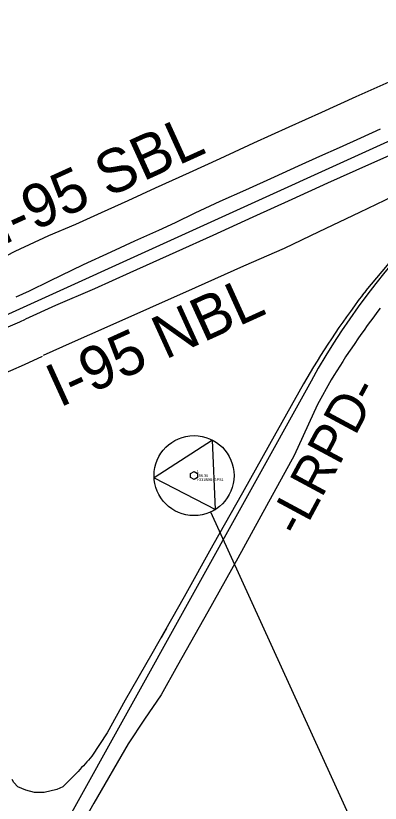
# Model space of a CAD drawing. Extents: x 2243531 to 2252747, y 658714 to 667210.
# Drawn here: x 2247806 to 2248142, y 662389 to 663115 of the extents above; entities that cross this region are included whole.
import ezdxf

# ---------------------------------------------------------------- set-up
doc = ezdxf.new("R2010")
doc.units = 0
for name, color, linetype in [('CTL GPS Vertical CELL', 7, 'Continuous'), ('CTL GPS Vertical Cogo Comment', 7, 'Continuous'), ('CTL GPS Vertical Cogo Elevation', 7, 'Continuous'), ('CTL GPS Vertical Cogo Number', 7, 'Continuous'), ('CTL NGS Horizontal CELL', 7, 'Continuous'), ('Exist Roads EOP', 7, 'Continuous'), ('Exist Roads EOP Text', 7, 'Continuous'), ('Prop Horizontal Alignment', 7, 'Continuous')]:
    doc.layers.add(name, color=color, linetype=linetype)

msp = doc.modelspace()

# ---------------------------------------------------------------- linework, layer by layer
at = {"layer": 'CTL GPS Vertical CELL'}
msp.add_line((2247970.45, 662691.36), (2247970.45, 662691.36), dxfattribs=at)
msp.add_lwpolyline([(2247967.22, 662693.23), (2247970.47, 662695.04), (2247973.72, 662693.26), (2247973.67, 662689.53), (2247970.42, 662687.64), (2247967.22, 662689.46)], close=True, dxfattribs=at)
at = {"layer": 'CTL NGS Horizontal CELL'}
for p, q in [((2247970.45, 662691.36), (2247970.45, 662691.36)), ((2247985.74, 662657.8), (2248187.57, 662214.89))]:
    msp.add_line(p, q, dxfattribs=at)
msp.add_lwpolyline([(2247933.59, 662689.43), (2247990.24, 662660.19), (2247987.36, 662724.13), (2247933.59, 662689.43)], dxfattribs=at)
msp.add_circle((2247970.45, 662691.36), 36.87, dxfattribs=at)
at = {"layer": 'Exist Roads EOP'}
msp.add_line((2248128.89, 662862.01), (2248125.5, 662857.61), dxfattribs=at)
for points in [[(2247790.71, 662890.62), (2247805.57, 662898.29), (2247836.78, 662912.86), (2247861.63, 662923.16), (2247885.32, 662933.83), (2247909.61, 662945.06), (2247935.04, 662956.66), (2247966.34, 662970.9), (2247994.49, 662983.87), (2248025.59, 662998.19), (2248058.08, 663012.97), (2248088.08, 663026.44), (2248119.82, 663041.08), (2248150.21, 663054.44), (2248181.1, 663069.6), (2248218.38, 663087.19), (2248245.39, 663099.49), (2248287.88, 663118.8), (2248325.22, 663134.87), (2248357.59, 663149.14), (2248375.51, 663157.12), (2248384.78, 663161.44)], [(2248461.34, 663127.8), (2248423.69, 663110.61), (2248387, 663094.02), (2248349.12, 663076.79), (2248316.15, 663062.19), (2248279.66, 663045.57), (2248238.72, 663026.91), (2248203.09, 663010.67), (2248166.49, 662993.47), (2248131.09, 662977.98), (2248093.34, 662960.9), (2248060.54, 662946.01), (2248024.51, 662929.58), (2247987.81, 662912.88), (2247953.6, 662897.46), (2247911.13, 662878.2), (2247878.83, 662863.52), (2247842.91, 662848.25), (2247815.2, 662835.56)], [(2248142.04, 663010.79), (2248123.7, 663002.54), (2248104.21, 662993.66), (2248086.01, 662985.57), (2248066.33, 662976.62), (2248044.2, 662966.53), (2248017.78, 662954.61), (2247994.22, 662943.99), (2247971.06, 662933.49), (2247952.96, 662924.57), (2247937.83, 662917.26), (2247915.51, 662907.4), (2247893.88, 662897.53), (2247868.29, 662885.73), (2247837.31, 662870.57), (2247818.47, 662861.37), (2247806.29, 662855.84)], [(2247831.65, 662802.33), (2247858.38, 662814.46), (2247890.52, 662828.54), (2247929.75, 662846.07), (2247971.89, 662864.9), (2248016.34, 662884.69), (2248053.87, 662901.09), (2248085.69, 662916.48), (2248123.17, 662934.34), (2248153.89, 662949.09), (2248186.42, 662964.72), (2248216.92, 662976.74), (2248221.9, 662965.48), (2248194.06, 662935.8), (2248165.12, 662904.72)], [(2248128.89, 662862.01), (2248165.12, 662904.72)], [(2247703.93, 662789.15), (2247704.62, 662789.23), (2247708.87, 662790.59), (2247723.15, 662796.8), (2247748.98, 662809.19), (2247767.16, 662818.57), (2247776.69, 662818.9), (2247809.98, 662833.15), (2247815.2, 662835.56)], [(2247712.22, 662747.88), (2247713.15, 662748.29), (2247727.42, 662754.69), (2247754.26, 662766.91), (2247764.74, 662771.77), (2247788.77, 662782.68), (2247801.57, 662788.25), (2247814.14, 662793.92), (2247830.73, 662801.46)], [(2248096.78, 662779.54), (2248084.07, 662756.84), (2248062.64, 662709.98), (2248037.34, 662663.46), (2248010.74, 662615.18), (2247983.18, 662565.69), (2247955.27, 662516.25), (2247940.12, 662489.33), (2247924.73, 662466.72), (2247909.76, 662444.13), (2247878.25, 662389.2), (2247865.93, 662367.55)], [(2248071.25, 662775.88), (2248039.92, 662719.99), (2248015.12, 662675.37), (2247987.84, 662627.09), (2247961.29, 662579.71), (2247931.67, 662527.1), (2247907.1, 662484.32), (2247890.37, 662454.17), (2247876.14, 662432.65)], [(2247945.11, 662550.47), (2247940.29, 662541.76)], [(2247849.52, 662404.52), (2247844.12, 662401.87), (2247832.33, 662399.25), (2247823.4, 662398.99), (2247815.41, 662401.25), (2247808.16, 662404.51), (2247804.34, 662408.28), (2247802.97, 662411.14)]]:
    msp.add_lwpolyline(points, dxfattribs=at)
for centre, major_axis, ratio, start_param, end_param in [((2248736.33, 662392.69), (-338.18, -691.09), 0.997611, 4.517336, 4.644929), ((2248728.98, 662396.71), (-514.69, -532.36), 0.998008, 4.827674, 4.935997)]:
    msp.add_ellipse(centre, major_axis=major_axis, ratio=ratio, start_param=start_param, end_param=end_param, dxfattribs=at)
msp.add_spline([(2247876.14, 662432.65), (2247863.72, 662418.65), (2247849.52, 662404.52)], degree=3, dxfattribs=at)
at = {"layer": 'Prop Horizontal Alignment'}
for p, q in [((2247500.8, 662705.02), (2249793.08, 663746.29)), ((2248078.23, 662778.57), (2247811.46, 662297.42))]:
    msp.add_line(p, q, dxfattribs=at)
msp.add_arc((2248668.56, 662451.26), 675, 114.43013, 150.99406, dxfattribs=at)

# ---------------------------------------------------------------- texts
at = {"layer": 'CTL GPS Vertical Cogo Comment'}
msp.add_text('I-3318BB-GPS1', height=2.5, dxfattribs=at).set_placement((2247972.95, 662686.36))
at = {"layer": 'CTL GPS Vertical Cogo Elevation'}
msp.add_text('156.30', height=2.5, dxfattribs=at).set_placement((2247972.95, 662690.11))
at = {"layer": 'CTL GPS Vertical Cogo Number'}
msp.add_text('1', height=2.5, dxfattribs=at).set_placement((2247972.95, 662693.86))
at = {"layer": 'Exist Roads EOP Text'}
for s, height, rotation, p in [('I-95 SBL', 40, 24.46002, (2247793.54, 662903.33)), ('I-95 NBL', 40, 24.46002, (2247846.4, 662753.72)), ('-LRPD-', 35, 61.70601, (2248068.32, 662633.4))]:
    msp.add_text(s, height=height, rotation=rotation, dxfattribs=at).set_placement(p)

doc.saveas('drawing.dxf')
